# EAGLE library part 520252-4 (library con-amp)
AMP connector
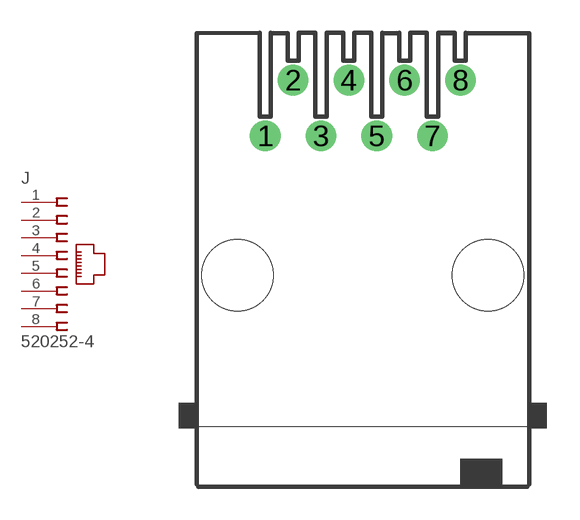
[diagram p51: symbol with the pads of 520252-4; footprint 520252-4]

Designator prefix J

## 520252-4 (MF: TYCO ELECTRONICS; MPN: 5520252-4; OC_FARNELL: 1557665; OC_NEWARK: 42K7224)  [520252-4]
1  1  pas
2  2  pas
3  3  pas
4  4  pas
5  5  pas
6  6  pas
7  7  pas
8  8  pas

## Footprint 520252-4 (pad centres in mm)
Modular Jack Keyed with Panel Stops
drill 0.889 round: 1 -4.445,6.35; 2 -3.175,8.89; 3 -1.905,6.35; 4 -0.635,8.89; 5 0.635,6.35; 6 1.905,8.89; 7 3.175,6.35; 8 4.445,8.89
hole 3.251 at -5.715,0
hole 3.251 at 5.715,0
